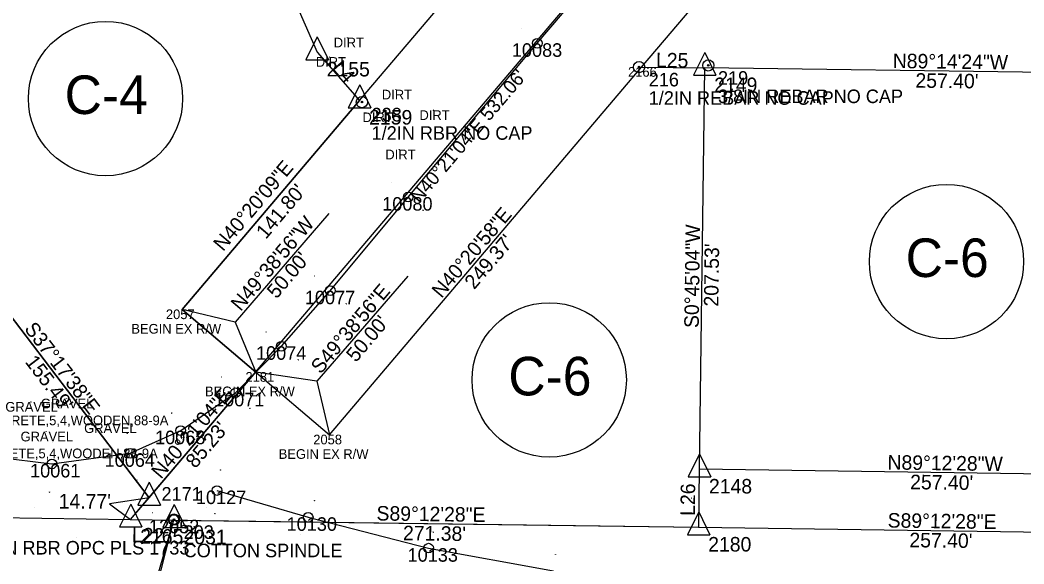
# Model space of a CAD drawing. Extents: x 1431802 to 1457777, y 1852108 to 1876350.
# Drawn here: x 1443925 to 1444444, y 1854914 to 1855196 of the extents above; entities that cross this region are included whole.
import ezdxf

# ---------------------------------------------------------------- set-up
doc = ezdxf.new("R2010")
doc.units = 0
for name, color, linetype in [('Default', 7, 'Continuous'), ('S_BRIDGE_ANNOT', 7, 'Continuous'), ('S_CAL_CORNER', 7, 'Continuous'), ('S_CAL_CORNER_ANNOT', 7, 'Continuous'), ('S_DRIVEWAY_ANNOT', 7, 'Continuous'), ('S_EXIST_ROW', 7, 'Continuous'), ('S_EXIST_ROW_ANNOT', 7, 'Continuous'), ('S_EXISTING_ALIGNMENT', 7, 'Continuous'), ('S_EXISTING_ALIGNMENT_ANNOT', 7, 'Continuous'), ('S_IRON_PIN', 7, 'Continuous'), ('S_IRON_PIN_ANNOT', 7, 'Continuous'), ('S_PROPERTY', 7, 'Continuous'), ('S_PROPERTY_ANNOT', 7, 'Continuous'), ('S_QSECTION', 7, 'Continuous'), ('S_RDW_PT_SYM', 7, 'Continuous')]:
    doc.layers.add(name, color=color, linetype=linetype)

msp = doc.modelspace()

# ---------------------------------------------------------------- linework, layer by layer
at = {"layer": 'Default'}
for points in [[(1444262.82, 1855174.77), (1444262.82, 1855174.82), (1444262.82, 1855174.77), (1444262.77, 1855174.77), (1444262.82, 1855174.77), (1444262.82, 1855174.72), (1444262.82, 1855174.77), (1444262.87, 1855174.77)], [(1444092.42, 1855168.94), (1444092.46, 1855168.97), (1444092.42, 1855168.94), (1444092.39, 1855168.98), (1444092.42, 1855168.94), (1444092.38, 1855168.91), (1444092.42, 1855168.94), (1444092.46, 1855168.9)], [(1444272.41, 1854948.34), (1444272.36, 1854948.34), (1444272.41, 1854948.34), (1444272.4, 1854948.29), (1444272.41, 1854948.34), (1444272.46, 1854948.34), (1444272.41, 1854948.34), (1444272.41, 1854948.39)], [(1443993.44, 1854940.95), (1443993.44, 1854941), (1443993.44, 1854940.95), (1443993.39, 1854940.95), (1443993.44, 1854940.95), (1443993.44, 1854940.9), (1443993.44, 1854940.95), (1443993.49, 1854940.95)], [(1444025.85, 1854940.5), (1444025.85, 1854940.55), (1444025.85, 1854940.5), (1444025.8, 1854940.5), (1444025.85, 1854940.5), (1444025.85, 1854940.45), (1444025.85, 1854940.5), (1444025.9, 1854940.5)]]:
    msp.add_lwpolyline(points, dxfattribs=at)
at = {"layer": 'S_CAL_CORNER'}
for p, q in [((1444078.72, 1855186.87), (1444072.84, 1855175.05)), ((1444078.72, 1855186.87), (1444084.53, 1855175.05)), ((1444279.16, 1855178.78), (1444273.29, 1855166.97)), ((1444279.16, 1855178.78), (1444284.97, 1855166.97)), ((1444072.84, 1855175.05), (1444084.53, 1855175.05)), ((1444273.29, 1855166.97), (1444284.97, 1855166.97)), ((1444100.68, 1855162.01), (1444094.81, 1855150.19)), ((1444100.68, 1855162.01), (1444106.5, 1855150.19)), ((1444094.81, 1855150.19), (1444106.5, 1855150.19)), ((1444276.44, 1854971.27), (1444270.56, 1854959.45)), ((1444276.44, 1854971.27), (1444282.25, 1854959.45)), ((1444270.56, 1854959.45), (1444282.25, 1854959.45)), ((1443991.82, 1854956.59), (1443985.94, 1854944.77)), ((1443991.82, 1854956.59), (1443997.63, 1854944.77)), ((1443982.26, 1854945.33), (1443976.38, 1854933.51)), ((1443982.26, 1854945.33), (1443988.07, 1854933.51)), ((1443985.94, 1854944.77), (1443997.63, 1854944.77)), ((1444004.69, 1854945.02), (1443998.82, 1854933.2)), ((1444004.69, 1854945.02), (1444010.51, 1854933.2)), ((1444276.05, 1854941.27), (1444270.17, 1854929.45)), ((1444276.05, 1854941.27), (1444281.86, 1854929.45)), ((1443976.38, 1854933.51), (1443988.07, 1854933.51)), ((1443998.82, 1854933.2), (1444010.51, 1854933.2)), ((1444270.17, 1854929.45), (1444281.86, 1854929.45))]:
    msp.add_line(p, q, dxfattribs=at)
at = {"layer": 'S_EXIST_ROW'}
for p, q in [((1444100.59, 1855154.03), (1444293.09, 1855380.54)), ((1444246.47, 1855171.24), (1444369.29, 1855315.79)), ((1444085.02, 1854981.19), (1444246.47, 1855171.24)), ((1444085.02, 1854981.19), (1444246.47, 1855171.24)), ((1444008.81, 1855045.93), (1444100.59, 1855154.03))]:
    msp.add_line(p, q, dxfattribs=at)
msp.add_lwpolyline([(1444008.81, 1855045.93), (1444046.91, 1855013.56), (1444085.02, 1854981.19)], dxfattribs=at)
at = {"layer": 'S_EXISTING_ALIGNMENT'}
for p, q in [((1443986.7, 1854942.69), (1444331.19, 1855348.17)), ((1444192.52, 1855183.54), (1444257.52, 1855260)), ((1444125.77, 1855104.02), (1444192.52, 1855183.54)), ((1444085.45, 1855055.61), (1444125.77, 1855104.02)), ((1444060.19, 1855026.91), (1444085.45, 1855055.61)), ((1444036.49, 1855002.84), (1444060.19, 1855026.91)), ((1444008.12, 1854983.27), (1444036.49, 1855002.84)), ((1443982.04, 1854971.58), (1444008.12, 1854983.27)), ((1443901.18, 1854970.96), (1443941.5, 1854966.08)), ((1443941.5, 1854966.08), (1443982.04, 1854971.58)), ((1444026.86, 1854952.32), (1444074.06, 1854938.48)), ((1443982.17, 1854937.35), (1443986.7, 1854942.69)), ((1444074.06, 1854938.48), (1444136.32, 1854922.52)), ((1443990.44, 1854888.01), (1444004.54, 1854937.19)), ((1444136.32, 1854922.52), (1444201, 1854910.83))]:
    msp.add_line(p, q, dxfattribs=at)
for centre in [(1444192.52, 1855183.54), (1444125.77, 1855104.02), (1444085.45, 1855055.61), (1444060.19, 1855026.91), (1444036.49, 1855002.84), (1444008.12, 1854983.27), (1443982.04, 1854971.58), (1443941.5, 1854966.08), (1444026.86, 1854952.32), (1444004.54, 1854937.19), (1444074.06, 1854938.48), (1444136.32, 1854922.52)]:
    msp.add_circle(centre, 2.5, dxfattribs=at)
at = {"layer": 'S_IRON_PIN'}
for centre, radius in [((1444245.19, 1855171.25), 2.91), ((1444245.19, 1855171.25), 0.411), ((1444245.19, 1855171.25), 0.262), ((1444245.19, 1855171.25), 0.212), ((1444245.19, 1855171.25), 0.145), ((1444245.19, 1855171.25), 0.0822), ((1444245.19, 1855171.25), 0.0581), ((1444281.01, 1855172.12), 2.91), ((1444281.01, 1855172.12), 0.411), ((1444281.01, 1855172.12), 0.262), ((1444281.01, 1855172.12), 0.212), ((1444281.01, 1855172.12), 0.145), ((1444281.01, 1855172.12), 0.0822), ((1444281.01, 1855172.12), 0.0581), ((1444101.84, 1855153.15), 2.91), ((1444101.84, 1855153.15), 0.411), ((1444101.84, 1855153.15), 0.262), ((1444101.84, 1855153.15), 0.212), ((1444101.84, 1855153.15), 0.145), ((1444101.84, 1855153.15), 0.0822), ((1444101.84, 1855153.15), 0.0581), ((1444004.62, 1854937.32), 2.91), ((1444004.62, 1854937.32), 0.411), ((1444004.62, 1854937.32), 0.262), ((1444004.62, 1854937.32), 0.212), ((1444004.62, 1854937.32), 0.145), ((1444004.62, 1854937.32), 0.0822), ((1444004.62, 1854937.32), 0.0581)]:
    msp.add_circle(centre, radius, dxfattribs=at)
at = {"layer": 'S_PROPERTY'}
for p, q in [((1444042.37, 1855262.18), (1444078.63, 1855178.89)), ((1444078.63, 1855178.89), (1444100.59, 1855154.03)), ((1444085.02, 1854981.19), (1444246.47, 1855171.24)), ((1444246.47, 1855171.24), (1444279.07, 1855170.8)), ((1444279.07, 1855170.8), (1444276.35, 1854963.29)), ((1444536.45, 1855167.39), (1444279.07, 1855170.8)), ((1444100.59, 1855154.03), (1444008.81, 1855045.93)), ((1444008.81, 1855045.93), (1444100.59, 1855154.03)), ((1443991.73, 1854948.61), (1443897.52, 1855072.31)), ((1443897.52, 1855072.31), (1443991.73, 1854948.61)), ((1444046.91, 1855013.56), (1444008.81, 1855045.93)), ((1444036.33, 1855039.33), (1444046.91, 1855013.56)), ((1443982.17, 1854937.35), (1444046.91, 1855013.56)), ((1443991.73, 1854948.61), (1444046.91, 1855013.56)), ((1444046.91, 1855013.56), (1444085.02, 1854981.19)), ((1444078.59, 1855008.86), (1444085.02, 1854981.19)), ((1444276.35, 1854963.29), (1444275.96, 1854933.29)), ((1444533.73, 1854959.73), (1444276.35, 1854963.29)), ((1443982.17, 1854937.35), (1443991.73, 1854948.61)), ((1443728.95, 1854940.85), (1443982.17, 1854937.35)), ((1443982.17, 1854937.35), (1444004.6, 1854937.04)), ((1443985.9, 1854863.78), (1444004.6, 1854937.04)), ((1444004.6, 1854937.04), (1444275.96, 1854933.29)), ((1444275.96, 1854933.29), (1444533.33, 1854929.73))]:
    msp.add_line(p, q, dxfattribs=at)
for points in [[(1444084.69, 1855095.54), (1444036.33, 1855039.33), (1444008.81, 1855045.93)], [(1444125.59, 1855063.1), (1444078.59, 1855008.86), (1444046.91, 1855013.56)], [(1443982.17, 1854937.35), (1444046.91, 1855013.56), (1444008.81, 1855045.93)], [(1443991.73, 1854948.61), (1443971.2, 1854945.42), (1443982.17, 1854937.35)]]:
    msp.add_lwpolyline(points, dxfattribs=at)
for centre in [(1443969.21, 1855154.96), (1444404.21, 1855070.69), (1444198.73, 1855009.49)]:
    msp.add_circle(centre, 39.9, dxfattribs=at)
at = {"layer": 'S_QSECTION'}
for p, q in [((1444004.6, 1854937.04), (1444046.99, 1854936.46)), ((1444046.99, 1854936.46), (1444275.96, 1854933.29))]:
    msp.add_line(p, q, dxfattribs=at)
at = {"layer": 'S_RDW_PT_SYM'}
for points in [[(1444184.19, 1855191), (1444184.19, 1855191.05), (1444184.19, 1855191), (1444184.14, 1855191), (1444184.19, 1855191), (1444184.19, 1855190.95), (1444184.19, 1855191), (1444184.24, 1855191)], [(1444094.47, 1855186.43), (1444094.47, 1855186.48), (1444094.47, 1855186.43), (1444094.42, 1855186.43), (1444094.47, 1855186.43), (1444094.47, 1855186.38), (1444094.47, 1855186.43), (1444094.52, 1855186.43)], [(1444085.2, 1855176.39), (1444085.2, 1855176.44), (1444085.2, 1855176.39), (1444085.15, 1855176.39), (1444085.2, 1855176.39), (1444085.2, 1855176.34), (1444085.2, 1855176.39), (1444085.25, 1855176.39)], [(1444200.45, 1855177.21), (1444200.45, 1855177.26), (1444200.45, 1855177.21), (1444200.4, 1855177.21), (1444200.45, 1855177.21), (1444200.45, 1855177.16), (1444200.45, 1855177.21), (1444200.5, 1855177.21)], [(1444119.35, 1855159.52), (1444119.35, 1855159.57), (1444119.35, 1855159.52), (1444119.3, 1855159.52), (1444119.35, 1855159.52), (1444119.35, 1855159.47), (1444119.35, 1855159.52), (1444119.4, 1855159.52)], [(1444109.31, 1855147.76), (1444109.31, 1855147.81), (1444109.31, 1855147.76), (1444109.26, 1855147.76), (1444109.31, 1855147.76), (1444109.31, 1855147.71), (1444109.31, 1855147.76), (1444109.36, 1855147.76)], [(1444138.79, 1855148.9), (1444138.79, 1855148.95), (1444138.79, 1855148.9), (1444138.74, 1855148.9), (1444138.79, 1855148.9), (1444138.79, 1855148.85), (1444138.79, 1855148.9), (1444138.84, 1855148.9)], [(1444121.16, 1855128.55), (1444121.16, 1855128.6), (1444121.16, 1855128.55), (1444121.11, 1855128.55), (1444121.16, 1855128.55), (1444121.16, 1855128.5), (1444121.16, 1855128.55), (1444121.21, 1855128.55)], [(1444117.29, 1855111.4), (1444117.29, 1855111.45), (1444117.29, 1855111.4), (1444117.24, 1855111.4), (1444117.29, 1855111.4), (1444117.29, 1855111.35), (1444117.29, 1855111.4), (1444117.34, 1855111.4)], [(1444133.46, 1855097.21), (1444133.46, 1855097.26), (1444133.46, 1855097.21), (1444133.41, 1855097.21), (1444133.46, 1855097.21), (1444133.46, 1855097.16), (1444133.46, 1855097.21), (1444133.51, 1855097.21)], [(1444077.23, 1855063.34), (1444077.23, 1855063.39), (1444077.23, 1855063.34), (1444077.18, 1855063.34), (1444077.23, 1855063.34), (1444077.23, 1855063.29), (1444077.23, 1855063.34), (1444077.28, 1855063.34)], [(1444093.78, 1855048.92), (1444093.78, 1855048.97), (1444093.78, 1855048.92), (1444093.72, 1855048.92), (1444093.78, 1855048.92), (1444093.78, 1855048.87), (1444093.78, 1855048.92), (1444093.82, 1855048.92)], [(1444052.35, 1855034.3), (1444052.35, 1855034.35), (1444052.35, 1855034.3), (1444052.3, 1855034.3), (1444052.35, 1855034.3), (1444052.35, 1855034.25), (1444052.35, 1855034.3), (1444052.4, 1855034.3)], [(1444068.94, 1855019.96), (1444068.94, 1855020.01), (1444068.94, 1855019.96), (1444068.89, 1855019.96), (1444068.94, 1855019.96), (1444068.94, 1855019.91), (1444068.94, 1855019.96), (1444068.99, 1855019.96)], [(1444029.08, 1855011.09), (1444029.08, 1855011.14), (1444029.08, 1855011.09), (1444029.03, 1855011.09), (1444029.08, 1855011.09), (1444029.08, 1855011.04), (1444029.08, 1855011.09), (1444029.13, 1855011.09)], [(1443930.67, 1854998.09), (1443930.67, 1854998.14), (1443930.67, 1854998.09), (1443930.61, 1854998.09), (1443930.67, 1854998.09), (1443930.67, 1854998.04), (1443930.67, 1854998.09), (1443930.72, 1854998.09)], [(1443949.08, 1854999.79), (1443949.08, 1854999.84), (1443949.08, 1854999.79), (1443949.03, 1854999.79), (1443949.08, 1854999.79), (1443949.08, 1854999.74), (1443949.08, 1854999.79), (1443949.13, 1854999.79)], [(1444043.95, 1854994.86), (1444043.95, 1854994.91), (1444043.95, 1854994.86), (1444043.9, 1854994.86), (1444043.95, 1854994.86), (1444043.95, 1854994.81), (1444043.95, 1854994.86), (1444044, 1854994.86)], [(1444003.48, 1854992.37), (1444003.48, 1854992.42), (1444003.48, 1854992.37), (1444003.43, 1854992.37), (1444003.48, 1854992.37), (1444003.48, 1854992.32), (1444003.48, 1854992.37), (1444003.53, 1854992.37)], [(1443971.45, 1854987.06), (1443971.45, 1854987.11), (1443971.45, 1854987.06), (1443971.4, 1854987.06), (1443971.45, 1854987.06), (1443971.45, 1854987.01), (1443971.45, 1854987.06), (1443971.5, 1854987.06)], [(1443938.56, 1854982.72), (1443938.56, 1854982.77), (1443938.56, 1854982.72), (1443938.51, 1854982.72), (1443938.56, 1854982.72), (1443938.56, 1854982.67), (1443938.56, 1854982.72), (1443938.61, 1854982.72)], [(1443980.46, 1854981.89), (1443980.46, 1854981.94), (1443980.46, 1854981.89), (1443980.41, 1854981.89), (1443980.46, 1854981.89), (1443980.46, 1854981.84), (1443980.46, 1854981.89), (1443980.51, 1854981.89)], [(1443941.82, 1854976.94), (1443941.82, 1854976.99), (1443941.82, 1854976.94), (1443941.78, 1854976.94), (1443941.82, 1854976.94), (1443941.82, 1854976.89), (1443941.82, 1854976.94), (1443941.88, 1854976.94)], [(1444013.97, 1854971.32), (1444013.97, 1854971.37), (1444013.97, 1854971.32), (1444013.92, 1854971.32), (1444013.97, 1854971.32), (1444013.97, 1854971.27), (1444013.97, 1854971.32), (1444014.02, 1854971.32)], [(1444028.77, 1854962.97), (1444028.77, 1854963.02), (1444028.77, 1854962.97), (1444028.72, 1854962.97), (1444028.77, 1854962.97), (1444028.77, 1854962.92), (1444028.77, 1854962.97), (1444028.82, 1854962.97)], [(1443985.39, 1854957.72), (1443985.39, 1854957.77), (1443985.39, 1854957.72), (1443985.34, 1854957.72), (1443985.39, 1854957.72), (1443985.39, 1854957.67), (1443985.39, 1854957.72), (1443985.44, 1854957.72)], [(1443940.29, 1854951.53), (1443940.29, 1854951.58), (1443940.29, 1854951.53), (1443940.24, 1854951.53), (1443940.29, 1854951.53), (1443940.29, 1854951.48), (1443940.29, 1854951.53), (1443940.34, 1854951.53)], [(1443932.33, 1854943.37), (1443932.33, 1854943.42), (1443932.33, 1854943.37), (1443932.28, 1854943.37), (1443932.33, 1854943.37), (1443932.33, 1854943.32), (1443932.33, 1854943.37), (1443932.38, 1854943.37)], [(1444021.61, 1854943.37), (1444021.61, 1854943.42), (1444021.61, 1854943.37), (1444021.56, 1854943.37), (1444021.61, 1854943.37), (1444021.61, 1854943.32), (1444021.61, 1854943.37), (1444021.66, 1854943.37)], [(1444077.37, 1854947.08), (1444077.37, 1854947.13), (1444077.37, 1854947.08), (1444077.32, 1854947.08), (1444077.37, 1854947.08), (1444077.37, 1854947.03), (1444077.37, 1854947.08), (1444077.42, 1854947.08)], [(1444015.15, 1854933.65), (1444015.15, 1854933.7), (1444015.15, 1854933.65), (1444015.1, 1854933.65), (1444015.15, 1854933.65), (1444015.15, 1854933.6), (1444015.15, 1854933.65), (1444015.2, 1854933.65)], [(1443954.02, 1854927.85), (1443954.02, 1854927.9), (1443954.02, 1854927.85), (1443953.97, 1854927.85), (1443954.02, 1854927.85), (1443954.02, 1854927.8), (1443954.02, 1854927.85), (1443954.07, 1854927.85)], [(1444070.24, 1854929.42), (1444070.24, 1854929.47), (1444070.24, 1854929.42), (1444070.19, 1854929.42), (1444070.24, 1854929.42), (1444070.24, 1854929.37), (1444070.24, 1854929.42), (1444070.29, 1854929.42)], [(1444138.76, 1854930.87), (1444138.76, 1854930.92), (1444138.76, 1854930.87), (1444138.71, 1854930.87), (1444138.76, 1854930.87), (1444138.76, 1854930.82), (1444138.76, 1854930.87), (1444138.81, 1854930.87)], [(1444202, 1854919.3), (1444202, 1854919.35), (1444202, 1854919.3), (1444201.95, 1854919.3), (1444202, 1854919.3), (1444202, 1854919.25), (1444202, 1854919.3), (1444202.05, 1854919.3)]]:
    msp.add_lwpolyline(points, dxfattribs=at)

# ---------------------------------------------------------------- texts
at = {"layer": 'S_BRIDGE_ANNOT'}
for p in [(1443865.37, 1854986.09), (1443859.85, 1854969.01)]:
    msp.add_text('23.34,1933,CONCRETE,5,4,WOODEN,88-9A', height=5, dxfattribs=at).set_placement(p)
at = {"layer": 'S_CAL_CORNER_ANNOT'}
for s, p in [('2155', (1444083.63, 1855166.39)), ('2149', (1444284.07, 1855158.3)), ('2159', (1444105.59, 1855141.53)), ('2148', (1444281.35, 1854950.79)), ('2165', (1443987.17, 1854924.85)), ('2031', (1444009.6, 1854924.54)), ('2180', (1444280.96, 1854920.79))]:
    msp.add_text(s, height=7.5, dxfattribs=at).set_placement(p)
at = {"layer": 'S_DRIVEWAY_ANNOT'}
for s, p in [('DIRT', (1444087.28, 1855181.43)), ('DIRT', (1444078.01, 1855171.39)), ('DIRT', (1444112.16, 1855154.52)), ('DIRT', (1444102.13, 1855142.76)), ('DIRT', (1444131.61, 1855143.9)), ('DIRT', (1444113.98, 1855123.55)), ('GRAVEL', (1443935.81, 1854994.79)), ('GRAVEL', (1443917.4, 1854993.09)), ('GRAVEL', (1443958.18, 1854982.06)), ('GRAVEL', (1443925.29, 1854977.72))]:
    msp.add_text(s, height=5, dxfattribs=at).set_placement(p)
at = {"layer": 'S_EXIST_ROW_ANNOT'}
for s, height, p in [('2166', 5, (1444239.48, 1855166.24)), ('2057', 5, (1444000.46, 1855040.93)), ('BEGIN EX R/W', 5, (1443982.59, 1855033.43)), ('2181', 5, (1444041.6, 1855008.56)), ('BEGIN EX R/W', 5, (1444020.69, 1855001.06)), ('2058', 5, (1444076.67, 1854976.19)), ('BEGIN EX R/W', 5, (1444058.8, 1854968.69)), ('2171', 7, (1443998.19, 1854947.08))]:
    msp.add_text(s, height=height, dxfattribs=at).set_placement(p)
at = {"layer": 'S_EXISTING_ALIGNMENT_ANNOT'}
for s, p in [('10083', (1444179.4, 1855176.54)), ('10080', (1444112.35, 1855097.02)), ('10077', (1444072.33, 1855048.61)), ('10074', (1444047.07, 1855019.91)), ('10071', (1444025.36, 1854995.84)), ('10068', (1443994.84, 1854976.27)), ('10064', (1443968.76, 1854964.58)), ('10061', (1443930.2, 1854959.08)), ('10127', (1444016, 1854945.32)), ('10130', (1444062.9, 1854931.48)), ('12052', (1443991.69, 1854930.19)), ('10133', (1444125.47, 1854915.52))]:
    msp.add_text(s, height=7, dxfattribs=at).set_placement(p)
msp.add_text('N40%%d21\'04"E 532.06\'', height=7, rotation=49.649, dxfattribs=at).set_placement((1444131.58, 1855100.47))
at = {"layer": 'S_IRON_PIN_ANNOT'}
for s, p in [('216', (1444250.19, 1855161.25)), ('219', (1444286.01, 1855162.12)), ('1/2IN REBAR NO CAP', (1444250.19, 1855151.75)), ('3/8IN REBAR NO CAP', (1444286.01, 1855152.62)), ('238', (1444106.84, 1855143.15)), ('1/2IN RBR NO CAP', (1444106.84, 1855133.65)), ('203', (1444009.62, 1854927.32)), ('1/2IN RBR OPC PLS 1733', (1443901.29, 1854919.24)), ('COTTON SPINDLE', (1444009.62, 1854917.82))]:
    msp.add_text(s, height=7, dxfattribs=at).set_placement(p)
at = {"layer": 'S_PROPERTY'}
for s, p in [('C-4', (1443948.08, 1855146.96)), ('C-6', (1444383.08, 1855062.69)), ('C-6', (1444177.59, 1855001.49))]:
    msp.add_text(s, height=19.95, dxfattribs=at).set_placement(p)
at = {"layer": 'S_PROPERTY_ANNOT'}
for s, rotation, p in [('L25', 359.2401, (1444253.92, 1855171.14)), ('N89%%d14\'24"W', 359.2401, (1444376.36, 1855170.76)), ('L4', 311.4566, (1444085.98, 1855170.58)), ("257.40'", 359.2401, (1444388.1, 1855160.61)), ('N40%%d20\'09"E', 49.6641, (1444030.04, 1855075.57)), ("141.80'", 49.6641, (1444052.14, 1855081.86)), ('N40%%d20\'58"E', 49.6506, (1444143, 1855051.37)), ('N49%%d38\'56"W', 49.649, (1444039.1, 1855044.61)), ('S0%%d45\'04"W', 89.2488, (1444276.06, 1855036.3)), ("249.37'", 49.6506, (1444159.95, 1855055.87)), ("207.53'", 89.2488, (1444286.21, 1855047.38)), ("50.00'", 49.649, (1444057.7, 1855051.05)), ('S49%%d38\'56"E', 49.649, (1444080.47, 1855012.15)), ("50.00'", 49.649, (1444098.76, 1855018.23)), ('S37%%d17\'38"E', 307.2938, (1443926.87, 1855035.83)), ("155.49'", 307.2938, (1443927.29, 1855018.78)), ('N40%%d21\'04"E', 49.649, (1443997.95, 1854957.86)), ("85.23'", 49.649, (1444015.7, 1854963.31)), ('N89%%d12\'28"W', 359.2077, (1444373.64, 1854963.19)), ("257.40'", 359.2077, (1444385.37, 1854953.03)), ('L26', 89.2488, (1444274.04, 1854939.18)), ('S89%%d12\'28"E', 359.2077, (1444109.36, 1854936.84)), ('S89%%d12\'28"E', 359.2077, (1444373.72, 1854933.19)), ('L22', 359.2077, (1443982.82, 1854925.58)), ("271.38'", 359.2077, (1444123.04, 1854926.65)), ("257.40'", 359.2077, (1444384.98, 1854923.03))]:
    msp.add_text(s, height=7.5, rotation=rotation, dxfattribs=at).set_placement(p)
msp.add_text("14.77'", height=7.5, dxfattribs=at).set_placement((1443945, 1854943.02))

doc.saveas('drawing.dxf')
